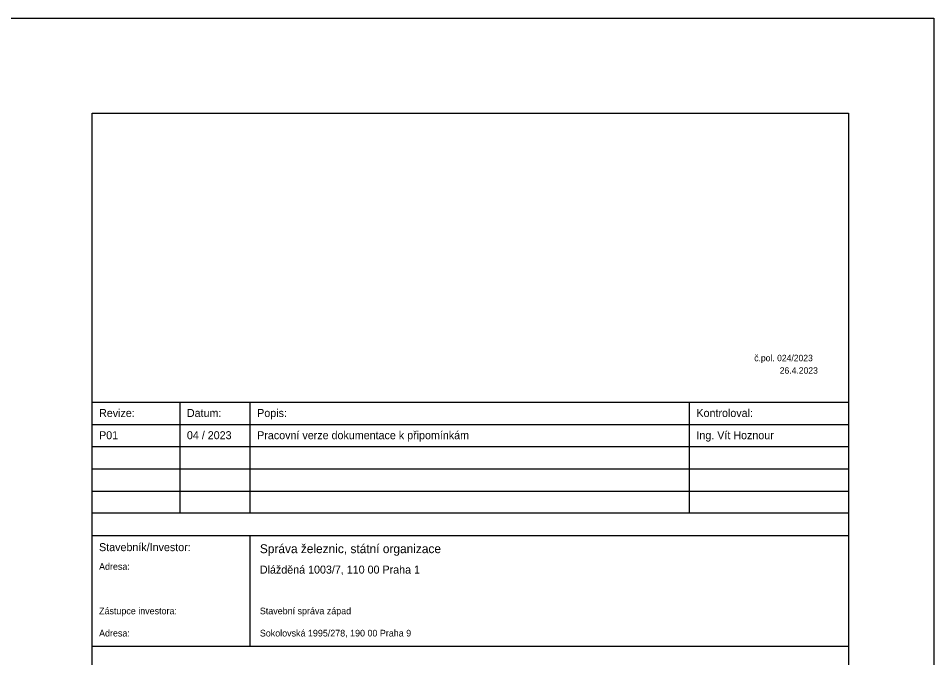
# Model space of a CAD drawing. Extents: x -757891 to -747391, y -1166581 to -1159156.
# Drawn here: x -752536 to -747391, y -1162753 to -1159156 of the extents above; entities that cross this region are included whole.
import ezdxf

# ---------------------------------------------------------------- set-up
doc = ezdxf.new("R2010")
doc.units = 0
for name, color, linetype in [('formát', 7, 'Continuous'), ('Popisove_pole', 7, 'Continuous'), ('SO 11-10-01_popisove_pole', 7, 'Continuous')]:
    doc.layers.add(name, color=color, linetype=linetype)

msp = doc.modelspace()

# ---------------------------------------------------------------- linework, layer by layer
at = {"layer": 'formát'}
msp.add_lwpolyline([(-752641.5, -1159156.4), (-747391.5, -1159156.4), (-747391.5, -1166581.4), (-752641.5, -1166581.4)], close=True, dxfattribs=at)
at = {"layer": 'SO 11-10-01_popisove_pole'}
for p, q in [((-751627.4, -1161940.2), (-751627.4, -1161315.2)), ((-751232.4, -1161940.2), (-751232.4, -1161315.2)), ((-748763.7, -1161940.2), (-748763.7, -1161315.2)), ((-752121.2, -1161440.2), (-747871.2, -1161440.2)), ((-752121.2, -1161565.2), (-747871.2, -1161565.2)), ((-752121.2, -1161690.2), (-747871.2, -1161690.2)), ((-752121.2, -1161815.2), (-747871.2, -1161815.2)), ((-751232.4, -1162690.2), (-751232.4, -1162065.2))]:
    msp.add_line(p, q, dxfattribs=at)
for points in [[(-752121.2, -1159690.2), (-747871.2, -1159690.2), (-747871.2, -1166190.2), (-752121.2, -1166190.2)], [(-752121.2, -1161315.2), (-747871.2, -1161315.2), (-747871.2, -1161940.2), (-752121.2, -1161940.2)], [(-752121.2, -1162065.2), (-747871.2, -1162065.2), (-747871.2, -1162690.2), (-752121.2, -1162690.2)]]:
    msp.add_lwpolyline(points, close=True, dxfattribs=at)

# ---------------------------------------------------------------- texts
at = {"layer": 'Popisove_pole'}
for s, p in [('č.pol. 024/2023', (-748400, -1161085.2)), ('26.4.2023', (-748256.7, -1161155.3))]:
    msp.add_text(s, height=36, rotation=360, dxfattribs=at).set_placement(p)
at = {"layer": 'SO 11-10-01_popisove_pole'}
for s, height, p in [('Revize:', 45, (-752082.5, -1161398.9)), ('Datum:', 45, (-751588.8, -1161398.9)), ('Popis:', 45, (-751193.8, -1161398.9)), ('Kontroloval:', 45, (-748725, -1161398.9)), ('P01', 45, (-752082.5, -1161523.9)), ('04 / 2023', 45, (-751588.8, -1161523.9)), ('Pracovní verze dokumentace k připomínkám', 45, (-751193.8, -1161523.9)), ('Ing. Vít Hoznour', 45, (-748725, -1161523.9)), ('Stavebník/Investor:', 45, (-752082.5, -1162153.4)), ('Správa železnic, státní organizace', 50, (-751178.8, -1162164.7)), ('Adresa:', 37.5, (-752082.5, -1162258.4)), ('Dlážděná 1003/7, 110 00 Praha 1', 45, (-751178.8, -1162279.7)), ('Zástupce investora:', 37.5, (-752082.5, -1162508.4)), ('Stavební správa západ', 37.5, (-751178.8, -1162508.4)), ('Adresa:', 37.5, (-752082.5, -1162633.4)), ('Sokolovská 1995/278, 190 00 Praha 9', 37.5, (-751178.8, -1162633.4))]:
    msp.add_text(s, height=height, rotation=360, dxfattribs=at).set_placement(p)

doc.saveas('drawing.dxf')
